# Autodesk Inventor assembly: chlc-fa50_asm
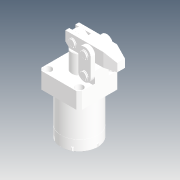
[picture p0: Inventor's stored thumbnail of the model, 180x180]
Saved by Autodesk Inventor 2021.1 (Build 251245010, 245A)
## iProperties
Company: Microsoft
Created: 2019-11
Part Number: chlc-fa50_asm
Description: STEP AP214
Document SubType Name: Assembly
Designer: user
Title: chlc-fa50_asm.STEP
Author: Windows
Revision Number: ÈÎºÎ
Sending System: SolidWorks 2015
Preprocessor: SwSTEP 2.0
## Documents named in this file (10)
- D:\Vault_2016\Projekty\Clamptek\Hydraulic\CHLC\CHLC-50\Inventor\CHLC-FA50\chlc-fa50_asm.iam
- D:\Vault_2016\Projekty\Clamptek\Hydraulic\CHLC\CHLC-50\Inventor\CHLC-FA50\CHLC-FA50-05.ipt
- D:\Vault_2016\Projekty\Clamptek\Hydraulic\CHLC\CHLC-50\Inventor\CHLC-FA50\CHLC-FA50-06.ipt
- D:\Vault_2016\Projekty\Clamptek\Hydraulic\CHLC\CHLC-50\Inventor\CHLC-FA50\CHLC-50-09.ipt
- D:\Vault_2016\Projekty\Clamptek\Hydraulic\CHLC\CHLC-50\Inventor\CHLC-FA50\CHLC-50-01.ipt
- D:\Vault_2016\Projekty\Clamptek\Hydraulic\CHLC\CHLC-50\Inventor\CHLC-FA50\CHLC-50-03.ipt
- D:\Vault_2016\Projekty\Clamptek\Hydraulic\CHLC\CHLC-50\Inventor\CHLC-FA50\CHLC-50-02.ipt
- D:\Vault_2016\Projekty\Clamptek\Hydraulic\CHLC\CHLC-50\Inventor\CHLC-FA50\CHLC-50-04.ipt
- D:\Vault_2016\Projekty\Clamptek\Hydraulic\CHLC\CHLC-50\Inventor\CHLC-FA50\CHLC-50-06.ipt
- D:\Vault_2016\Projekty\Clamptek\Hydraulic\CHLC\CHLC-50\Inventor\CHLC-FA50\M6LC.ipt
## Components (21 placed, 21 different names)
1. CHLC-FA50-05_1
2. CHLC-FA50-06_2
3. CHLC-50-09_3
4. CHLC-50-01_4
5. CHLC-50-03_5
6. CHLC-50-03_6
7. CHLC-50-02_7
8. CHLC-50-04_8
9. CHLC-50-04_9
10. CHLC-50-06_10
11. CHLC-50-06_11
12. CHLC-50-06_12
13. CHLC-50-06_13
14. CHLC-50-06_14
15. CHLC-50-06_15
16. M6LC_16
17. M6LC_17
18. M6LC_18
19. M6LC_19
20. M6LC_20
21. M6LC_21
